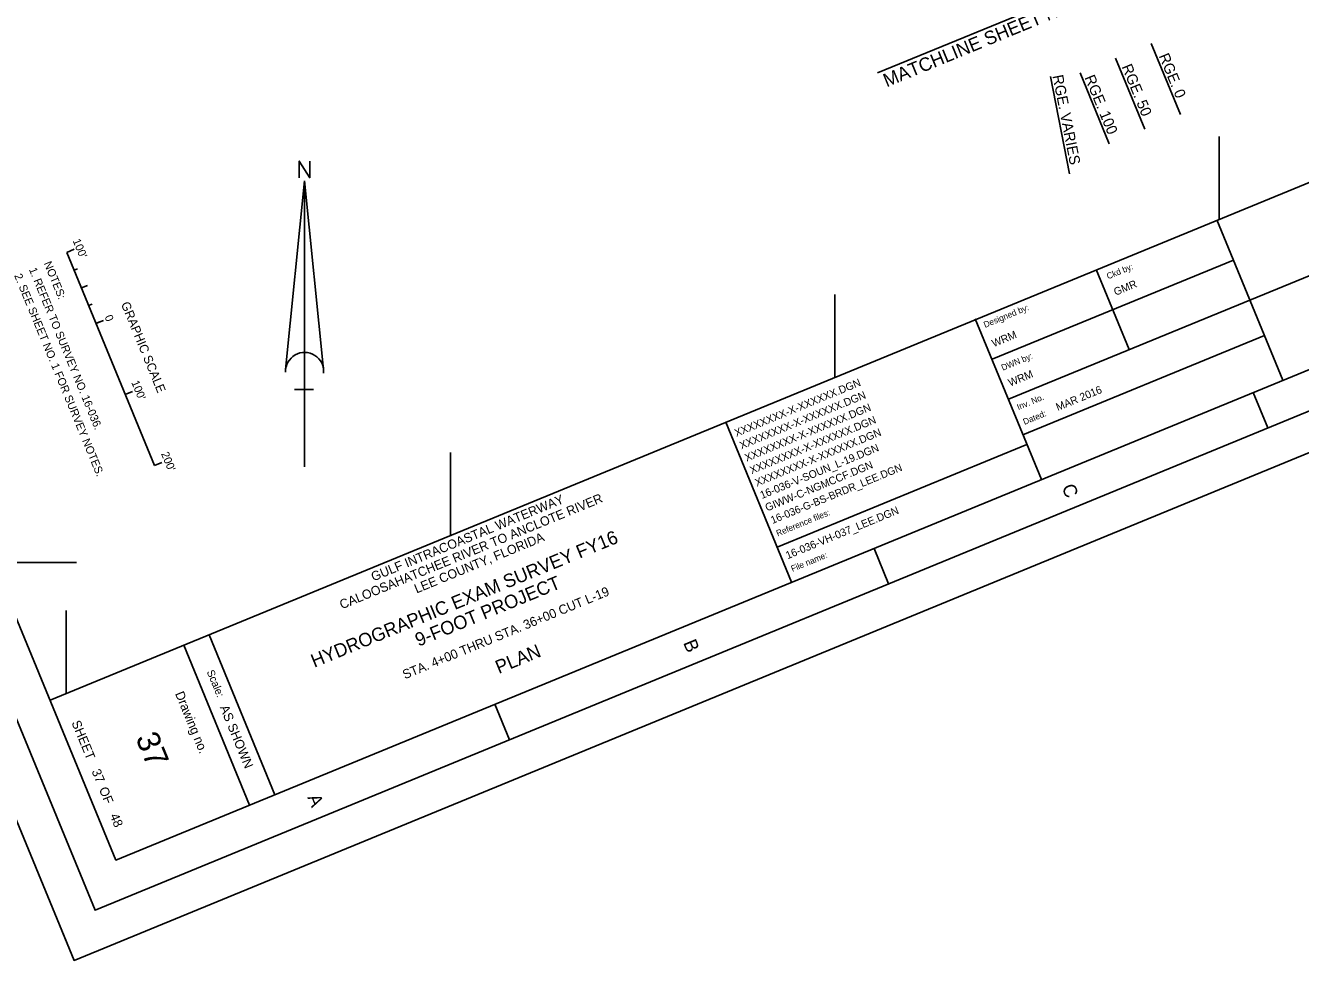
# Model space of a CAD drawing. Extents: x 580836 to 585655, y 849482 to 854845.
# Drawn here: x 582447 to 584106, y 849482 to 850699 of the extents above; entities that cross this region are included whole.
import ezdxf

# ---------------------------------------------------------------- set-up
doc = ezdxf.new("R2010")
doc.units = 0
for name, color, linetype in [('G-ANNO-NPLT', 7, 'Continuous'), ('G-ANNO-TEXT-DRWG', 7, 'Continuous'), ('G-ANNO-TEXT-PROJ', 7, 'Continuous'), ('G-ANNO-TEXT-TTLB', 7, 'Continuous'), ('G-ANNO-TTLB', 7, 'Continuous'), ('V-ALGN-TEXT', 7, 'Continuous'), ('V-ANNO-MATC', 7, 'Continuous'), ('V-ANNO-MATC-IDEN', 7, 'Continuous'), ('V-ANNO-NOTE', 7, 'Continuous'), ('V-ANNO-SYMB', 7, 'Continuous'), ('V-TOPO-COOR-STAT', 7, 'Continuous')]:
    doc.layers.add(name, color=color, linetype=linetype)

msp = doc.modelspace()

# ---------------------------------------------------------------- linework, layer by layer
at = {"layer": 'G-ANNO-NPLT'}
msp.add_lwpolyline([(583980.5, 854844.8), (585654.5, 850775.7), (582510.3, 849482.1), (580836.2, 853551.2)], close=True, dxfattribs=at)
msp.add_lwpolyline([(582556.6, 849501), (582510.3, 849482), (582491.3, 849528.2)], dxfattribs=at)
at = {"layer": 'G-ANNO-TTLB'}
for p, q in [((585438.4, 851038.2), (582479.1, 849820.7)), ((583725.9, 850212.7), (584521, 850539.1)), ((583997.1, 850446.1), (584083, 850237.3)), ((583704.6, 850264.5), (584018.8, 850393.4)), ((583840, 850381.5), (583883, 850277.2)), ((583682.8, 850317.3), (583768.9, 850108)), ((584059.1, 850295.5), (583744.9, 850166.3)), ((584063.3, 850175.1), (584044.3, 850221.3)), ((583358.3, 850182.4), (583443.9, 849974.4)), ((583750.1, 850153.6), (583425.2, 850019.9)), ((583570.1, 849972.2), (583551.1, 850018.4)), ((582686, 849905.9), (582771.6, 849697.8)), ((582653, 849892.3), (582738.6, 849684.2)), ((583076.9, 849769.3), (583057.9, 849815.5))]:
    msp.add_line(p, q, dxfattribs=at)
for points in [[(580901.5, 853523.9), (582537.5, 849547.4), (585589.3, 850802.9), (583953.2, 854779.5)], [(585524, 850830.1), (583954.6, 854644.9), (580995.3, 853427.4), (582564.7, 849612.6)]]:
    msp.add_lwpolyline(points, close=True, dxfattribs=at)
at = {"layer": 'V-ALGN-TEXT'}
for p, q in [((583911.6, 850675.4), (583949.7, 850582.9)), ((583865.4, 850656.4), (583903.4, 850563.9)), ((583780.5, 850632.7), (583805.6, 850505.7)), ((583819.1, 850637.4), (583857.2, 850544.9))]:
    msp.add_line(p, q, dxfattribs=at)
at = {"layer": 'V-ANNO-MATC'}
msp.add_line((584099.9, 850861), (583555.6, 850637.1), dxfattribs=at)
at = {"layer": 'V-ANNO-NOTE'}
for p, q in [((582500.7, 850403.6), (582510.3, 850407.6)), ((582500.7, 850403.6), (582614.8, 850126.2)), ((582510.2, 850380.5), (582514.6, 850382.3)), ((582519.7, 850357.4), (582527.6, 850360.6)), ((582529.2, 850334.3), (582533.6, 850336.1)), ((582538.7, 850311.1), (582548.4, 850315.1)), ((582538.7, 850311.1), (582548.4, 850315.1)), ((582538.7, 850311.1), (582543.3, 850313)), ((582576.8, 850218.7), (582586.4, 850222.6)), ((582614.8, 850126.2), (582624.5, 850130.2))]:
    msp.add_line(p, q, dxfattribs=at)
at = {"layer": 'V-ANNO-SYMB'}
for p, q in [((582785.5, 850251.1), (582810.2, 850496.8)), ((582810.2, 850124.5), (582810.2, 850496.8)), ((582834.9, 850251.1), (582810.2, 850496.8)), ((582821.9, 850225), (582797.1, 850225))]:
    msp.add_line(p, q, dxfattribs=at)
msp.add_lwpolyline([(582803.3, 850500.8), (582803.3, 850522.5), (582816.8, 850500.8), (582816.8, 850522.5)], dxfattribs=at)
msp.add_arc((582810.2, 850248.6), 24.8, 355.2984, 182.0673, dxfattribs=at)
at = {"layer": 'V-TOPO-COOR-STAT'}
for p, q in [((584000, 850446.5), (584000, 850554.6)), ((583500, 850240.7), (583500, 850348.9)), ((583000, 850035), (583000, 850143.2)), ((582405.3, 850000), (582513.5, 850000)), ((582500, 849829.3), (582500, 849937.5))]:
    msp.add_line(p, q, dxfattribs=at)

# ---------------------------------------------------------------- texts
at = {"layer": 'G-ANNO-TEXT-DRWG'}
for s, height, rotation, p in [('GMR', 10, 22.363, (583865.4, 850347)), ('WRM', 10, 22.363, (583706.8, 850280.1)), ('WRM', 10, 22.363, (583728.2, 850228.8)), ('XXXXXXXX-X-XXXXXX.DGN', 10, 22.363, (583372, 850163.4)), ('XXXXXXXX-X-XXXXXX.DGN', 10, 22.363, (583378.6, 850147.2)), ('XXXXXXXX-X-XXXXXX.DGN', 10, 22.363, (583385.3, 850131.1)), ('XXXXXXXX-X-XXXXXX.DGN', 10, 22.363, (583391.9, 850114.9)), ('XXXXXXXX-X-XXXXXX.DGN', 10, 22.363, (583398.6, 850098.7)), ('16-036-V-SOUN_L-19.DGN', 10, 22.363, (583405.2, 850082.5)), ('GIWW-C-NGMCCF.DGN', 10, 22.363, (583411.9, 850066.3)), ('16-036-VH-037_LEE.DGN', 10, 22.363, (583438.6, 850004.1)), ('STA. 4+00 THRU STA. 36+00 CUT L-19', 12, 22.363, (582940.6, 849847.9)), ('PLAN', 17.5, 22.363, (583062.8, 849854.8)), ('37', 30, 292.363, (582589.8, 849771.8)), (' 37          48', 12, 292.363, (582531.1, 849732.4))]:
    msp.add_text(s, height=height, rotation=rotation, dxfattribs=at).set_placement(p)
at = {"layer": 'G-ANNO-TEXT-PROJ'}
for s, height, p in [('MAR 2016', 10, (583790.2, 850197.1)), ('16-036-G-BS-BRDR_LEE.DGN', 9.8, (583419, 850050.1)), ('CALOOSAHATCHEE RIVER TO ANCLOTE RIVER', 12, (582858.7, 849939)), ('GULF INTRACOASTAL WATERWAY', 12, (582899.7, 849975.3)), ('HYDROGRAPHIC EXAM SURVEY FY16', 17.5, (582822.8, 849862.9)), ('LEE COUNTY, FLORIDA', 12, (582955.9, 849959.6)), ('9-FOOT PROJECT', 17.5, (582958.4, 849890.3))]:
    msp.add_text(s, height=height, rotation=22.363, dxfattribs=at).set_placement(p)
at = {"layer": 'G-ANNO-TEXT-TTLB'}
for s, height, rotation, p in [('Ckd by:', 8, 22.363, (583855.7, 850368.4)), ('Designed by:', 8, 22.363, (583695.6, 850305.2)), ('DWN by:', 8, 22.363, (583718.6, 850249.5)), ('Inv. No.', 8, 22.363, (583738.9, 850198.2)), ('Dated:', 8, 22.363, (583746.9, 850179)), ('Reference files:', 8, 22.363, (583425.8, 850033.8)), ('File name:', 8, 22.363, (583445, 849987.7)), ('Scale:', 10, 292.363, (582682.6, 849857.8)), ('Drawing no.', 12, 292.363, (582641.4, 849829.3)), ('AS SHOWN', 12, 292.363, (582699.6, 849811.5)), ('SHEET         OF', 12, 292.363, (582506.7, 849791.6))]:
    msp.add_text(s, height=height, rotation=rotation, dxfattribs=at).set_placement(p)
at = {"layer": 'G-ANNO-TTLB'}
for s, p in [('C', (583795, 850098)), ('B', (583302.5, 849895.6)), ('A', (582813.5, 849694.4))]:
    msp.add_text(s, height=17.5, rotation=292.363, dxfattribs=at).set_placement(p)
at = {"layer": 'V-ALGN-TEXT'}
for s, rotation, p in [('RGE. 0', 292.363, (583921.3, 850659.3)), ('RGE. 50', 292.363, (583873, 850645.3)), ('RGE. VARIES', 281.1813, (583783.2, 850633.3)), ('RGE. 100', 292.363, (583824.7, 850631.2))]:
    msp.add_text(s, height=13.92, rotation=rotation, dxfattribs=at).set_placement(p)
at = {"layer": 'V-ANNO-MATC-IDEN'}
msp.add_text('MATCHLINE SHEET NO. 036 LEE STA. 4+00', height=17.52, rotation=22.363, dxfattribs=at).set_placement((583567.5, 850618.3))
at = {"layer": 'V-ANNO-NOTE'}
for s, height, p in [("100'", 10.42, (582508.2, 850418.9)), ('NOTES:', 10.42, (582470.6, 850389.4)), ('2. SEE SHEET NO. 1 FOR SURVEY NOTES.', 10.416, (582432.1, 850373.5)), ('1. REFER TO SURVEY NO. 16-036.', 10.416, (582451.3, 850381.4)), ('GRAPHIC SCALE', 11.666, (582571, 850336.5)), ('0', 10.4, (582549.7, 850319.7)), ("100'", 10.42, (582584.5, 850234.4)), ("200'", 10.42, (582623.2, 850141.6))]:
    msp.add_text(s, height=height, rotation=292.363, dxfattribs=at).set_placement(p)

doc.saveas('drawing.dxf')
